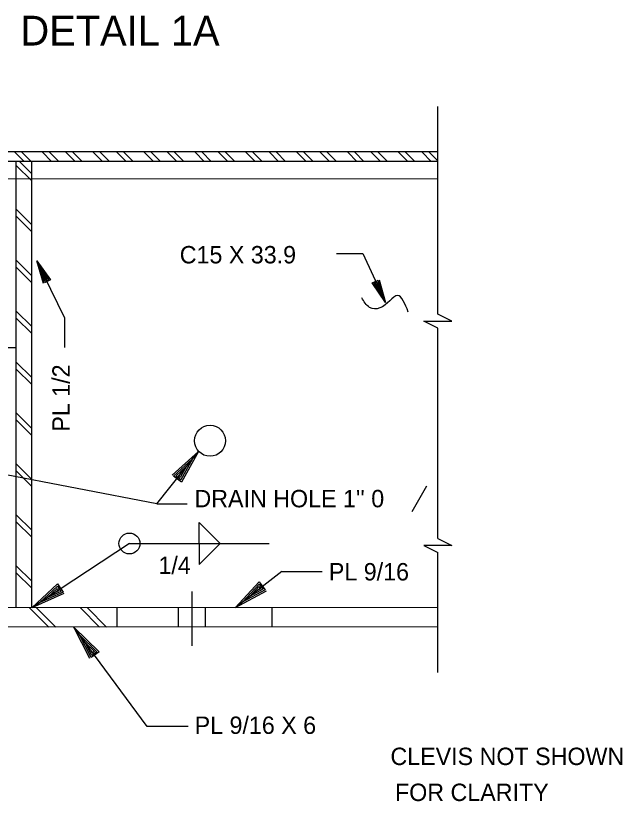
# Model space of a CAD drawing. Extents: x 0.1 to 13.5, y 0.1 to 9.5.
# Drawn here: x 3.214 to 4.844, y 3.195 to 5.304 of the extents above; entities that cross this region are included whole.
import ezdxf

# ---------------------------------------------------------------- set-up
doc = ezdxf.new("R2010")
doc.units = 0
for name, color, linetype in [('Level 1', 7, 'Continuous'), ('Level 13', 7, 'Continuous'), ('Level 25', 7, 'Continuous'), ('Level 3', 7, 'Continuous'), ('Level 44', 7, 'Continuous'), ('Level 50', 7, 'Continuous')]:
    doc.layers.add(name, color=color, linetype=linetype)

msp = doc.modelspace()

# ---------------------------------------------------------------- linework, layer by layer
at = {"layer": 'Level 1'}
msp.add_spline([(4.2688, 4.5088), (4.2398, 4.5531), (4.1925, 4.5197), (4.1649, 4.5213), (4.1435, 4.5474)], degree=3, dxfattribs=at)
at = {"layer": 'Level 13'}
for points in [[(4.3479, 4.4655), (4.3104, 4.4841), (4.3853, 4.4841), (4.3479, 4.5028)], [(4.3479, 3.9008), (4.3854, 3.8821), (4.3105, 3.8821), (4.3479, 3.8634)]]:
    msp.add_lwpolyline(points, dxfattribs=at)
at = {"layer": 'Level 25'}
for p, q in [((4.3479, 4.5028), (4.3479, 5.0608)), ((4.3479, 4.9394), (2.3893, 4.9382)), ((4.3479, 4.9133), (2.3397, 4.9121)), ((3.2154, 3.7147), (3.2154, 4.9126)), ((3.257, 3.7147), (3.257, 4.9127)), ((4.3479, 4.8664), (2.6838, 4.8654)), ((4.3479, 3.9008), (4.3479, 4.4655)), ((3.2154, 4.4126), (2.2087, 4.412)), ((4.2787, 3.9736), (4.3183, 4.0421)), ((3.707, 3.9436), (3.7629, 3.8878)), ((3.707, 3.8874), (3.707, 3.9436)), ((3.5195, 3.8874), (3.257, 3.7147)), ((3.5195, 3.8874), (3.8946, 3.8874)), ((3.707, 3.8874), (3.707, 3.8311)), ((3.707, 3.8311), (3.7629, 3.887)), ((4.3479, 3.5407), (4.3479, 3.8634)), ((4.3486, 3.7154), (1.8752, 3.7139)), ((3.257, 3.7147), (3.257, 3.7147)), ((3.2787, 3.729), (3.2787, 3.729)), ((3.4862, 3.6628), (3.4862, 3.7149)), ((3.9029, 3.6631), (3.9029, 3.7151)), ((4.3486, 3.6633), (1.8752, 3.6618))]:
    msp.add_line(p, q, dxfattribs=at)
msp.add_lwpolyline([(3.3437, 3.7532), (3.257, 3.7147), (3.3266, 3.7791), (3.3412, 3.7569), (3.2787, 3.729), (3.326, 3.7727), (3.3354, 3.7585), (3.2996, 3.7428), (3.3254, 3.7663), (3.3293, 3.7605), (3.3214, 3.757)], dxfattribs=at)
for centre, radius in [((3.736, 4.1633), 0.0417), ((3.5195, 3.8874), 0.0281)]:
    msp.add_circle(centre, radius, dxfattribs=at)
at = {"layer": 'Level 3'}
for p, q in [((3.2704, 4.6464), (3.2704, 4.6464)), ((3.278, 4.6308), (3.278, 4.6308)), ((4.1999, 4.5505), (4.1999, 4.5505)), ((4.2071, 4.5348), (4.2071, 4.5348))]:
    msp.add_line(p, q, dxfattribs=at)
for points in [[(4.0756, 4.6663), (4.1468, 4.6663), (4.2071, 4.5348)], [(3.3461, 4.4139), (3.3461, 4.4923), (3.2704, 4.6464)], [(3.2886, 4.5859), (3.2704, 4.6464), (3.3072, 4.595), (3.2913, 4.5872), (3.278, 4.6308), (3.303, 4.5959), (3.2928, 4.5909), (3.2854, 4.6159), (3.2988, 4.5968), (3.2946, 4.5948), (3.293, 4.6003)], [(4.1905, 4.5957), (4.2071, 4.5348), (4.1717, 4.5871), (4.1878, 4.5945), (4.1999, 4.5505), (4.1759, 4.5861), (4.1862, 4.5908), (4.1929, 4.5657), (4.18, 4.5851), (4.1842, 4.587), (4.1857, 4.5814)], [(3.6772, 3.396), (3.5669, 3.396), (3.3702, 3.6627)]]:
    msp.add_lwpolyline(points, dxfattribs=at)
at = {"layer": 'Level 44'}
for p, q in [((3.2368, 4.9133), (3.212, 4.9382)), ((3.2557, 4.9133), (3.2308, 4.9382)), ((3.3105, 4.9133), (3.2857, 4.9382)), ((3.3294, 4.9133), (3.3045, 4.9382)), ((3.3736, 4.9133), (3.3487, 4.9382)), ((3.3924, 4.9133), (3.3675, 4.9382)), ((3.4473, 4.9133), (3.4224, 4.9382)), ((3.4661, 4.9133), (3.4412, 4.9382)), ((3.5103, 4.9133), (3.4854, 4.9382)), ((3.5291, 4.9133), (3.5042, 4.9382)), ((3.584, 4.9133), (3.5591, 4.9382)), ((3.6028, 4.9133), (3.5779, 4.9382)), ((3.647, 4.9133), (3.6221, 4.9382)), ((3.6658, 4.9133), (3.6409, 4.9382)), ((3.7207, 4.9133), (3.6958, 4.9382)), ((3.7395, 4.9133), (3.7146, 4.9382)), ((3.7837, 4.9133), (3.7588, 4.9382)), ((3.8025, 4.9133), (3.7777, 4.9382)), ((3.8574, 4.9133), (3.8325, 4.9382)), ((3.8762, 4.9133), (3.8514, 4.9382)), ((3.9204, 4.9133), (3.8955, 4.9382)), ((3.9392, 4.9133), (3.9144, 4.9382)), ((3.9941, 4.9133), (3.9692, 4.9382)), ((4.0129, 4.9133), (3.9881, 4.9382)), ((4.0571, 4.9133), (4.0322, 4.9382)), ((4.0759, 4.9133), (4.0511, 4.9382)), ((4.1308, 4.9133), (4.1059, 4.9382)), ((4.1496, 4.9133), (4.1248, 4.9382)), ((4.1938, 4.9133), (4.1689, 4.9382)), ((4.2126, 4.9133), (4.1878, 4.9382)), ((4.2675, 4.9133), (4.2426, 4.9382)), ((4.2864, 4.9133), (4.2615, 4.9382)), ((4.3305, 4.9133), (4.3056, 4.9382)), ((4.3479, 4.9148), (4.3245, 4.9382)), ((3.257, 4.8609), (3.2154, 4.9026)), ((3.257, 4.8798), (3.2242, 4.9126)), ((3.257, 4.7431), (3.2154, 4.7848)), ((3.257, 4.7242), (3.2154, 4.7659)), ((3.257, 4.6064), (3.2154, 4.6481)), ((3.257, 4.5875), (3.2154, 4.6292)), ((3.257, 4.4697), (3.2154, 4.5114)), ((3.257, 4.4508), (3.2154, 4.4925)), ((3.257, 4.333), (3.2154, 4.3746)), ((3.257, 4.3141), (3.2154, 4.3558)), ((3.257, 4.1963), (3.2154, 4.2379)), ((3.257, 4.1774), (3.2154, 4.2191)), ((3.5935, 3.9938), (2.782, 4.1501)), ((3.5935, 3.9938), (3.7047, 4.1348)), ((3.257, 4.0596), (3.2154, 4.1012)), ((3.257, 4.0407), (3.2154, 4.0824)), ((3.5935, 3.9938), (3.6746, 3.9938)), ((3.257, 3.9229), (3.2154, 3.9645)), ((3.257, 3.904), (3.2154, 3.9457)), ((3.257, 3.7861), (3.2154, 3.8278)), ((3.257, 3.7673), (3.2154, 3.809)), ((3.9289, 3.8118), (3.8032, 3.7151)), ((3.9289, 3.8118), (4.0377, 3.8118)), ((3.6878, 3.6129), (3.6878, 3.7588)), ((3.3028, 3.6628), (3.251, 3.7146)), ((3.3216, 3.6628), (3.2698, 3.7146)), ((3.4395, 3.6628), (3.3877, 3.7146)), ((3.4583, 3.6628), (3.4065, 3.7146)), ((3.6514, 3.6629), (3.6514, 3.715)), ((3.7243, 3.6629), (3.7243, 3.715))]:
    msp.add_line(p, q, dxfattribs=at)
at = {"layer": 'Level 50'}
for p, q in [((3.7047, 4.1348), (3.7047, 4.1348)), ((3.6886, 4.1144), (3.6886, 4.1144)), ((3.8032, 3.7151), (3.8032, 3.7151)), ((3.8238, 3.7309), (3.8238, 3.7309)), ((3.3702, 3.6627), (3.3702, 3.6627)), ((3.3856, 3.6418), (3.3856, 3.6418))]:
    msp.add_line(p, q, dxfattribs=at)
for points in [[(3.6347, 4.071), (3.7047, 4.1348), (3.659, 4.0518), (3.6382, 4.0682), (3.6886, 4.1144), (3.6575, 4.058), (3.6442, 4.0685), (3.6731, 4.0947), (3.6561, 4.0642), (3.6506, 4.0686), (3.657, 4.0743)], [(3.8868, 3.7598), (3.8032, 3.7151), (3.8679, 3.7844), (3.884, 3.7634), (3.8238, 3.7309), (3.8677, 3.778), (3.8781, 3.7645), (3.8436, 3.7462), (3.8676, 3.7716), (3.8719, 3.766), (3.8642, 3.762)], [(3.4132, 3.5783), (3.3702, 3.6627), (3.4381, 3.5967), (3.4168, 3.581), (3.3856, 3.6418), (3.4318, 3.5969), (3.4181, 3.5868), (3.4004, 3.6217), (3.4253, 3.5972), (3.4197, 3.593), (3.4159, 3.6008)]]:
    msp.add_lwpolyline(points, dxfattribs=at)

# ---------------------------------------------------------------- texts
at = {"layer": 'Level 1'}
for s, height, p in [('C15 X 33.9', 0.0467, (3.6547, 4.6394)), ('1/4', 0.0467, (3.5974, 3.8055)), ('PL 9/16', 0.0467, (4.0553, 3.7882)), ('PL 9/16 X 6', 0.046698, (3.6947, 3.3762))]:
    msp.add_text(s, height=height, dxfattribs=at).set_placement(p)
at = {"layer": 'Level 25'}
for s, height, p in [('DETAIL 1A', 0.08, (3.2267, 5.2244)), ("DRAIN HOLE 1'' 0", 0.046698, (3.6942, 3.9846)), ('CLEVIS NOT SHOWN', 0.046698, (4.2208, 3.2926)), ('FOR CLARITY', 0.046698, (4.233, 3.196))]:
    msp.add_text(s, height=height, dxfattribs=at).set_placement(p)
msp.add_text('PL 1/2', height=0.0467, rotation=90, dxfattribs=at).set_placement((3.3591, 4.1877))

doc.saveas('drawing.dxf')
